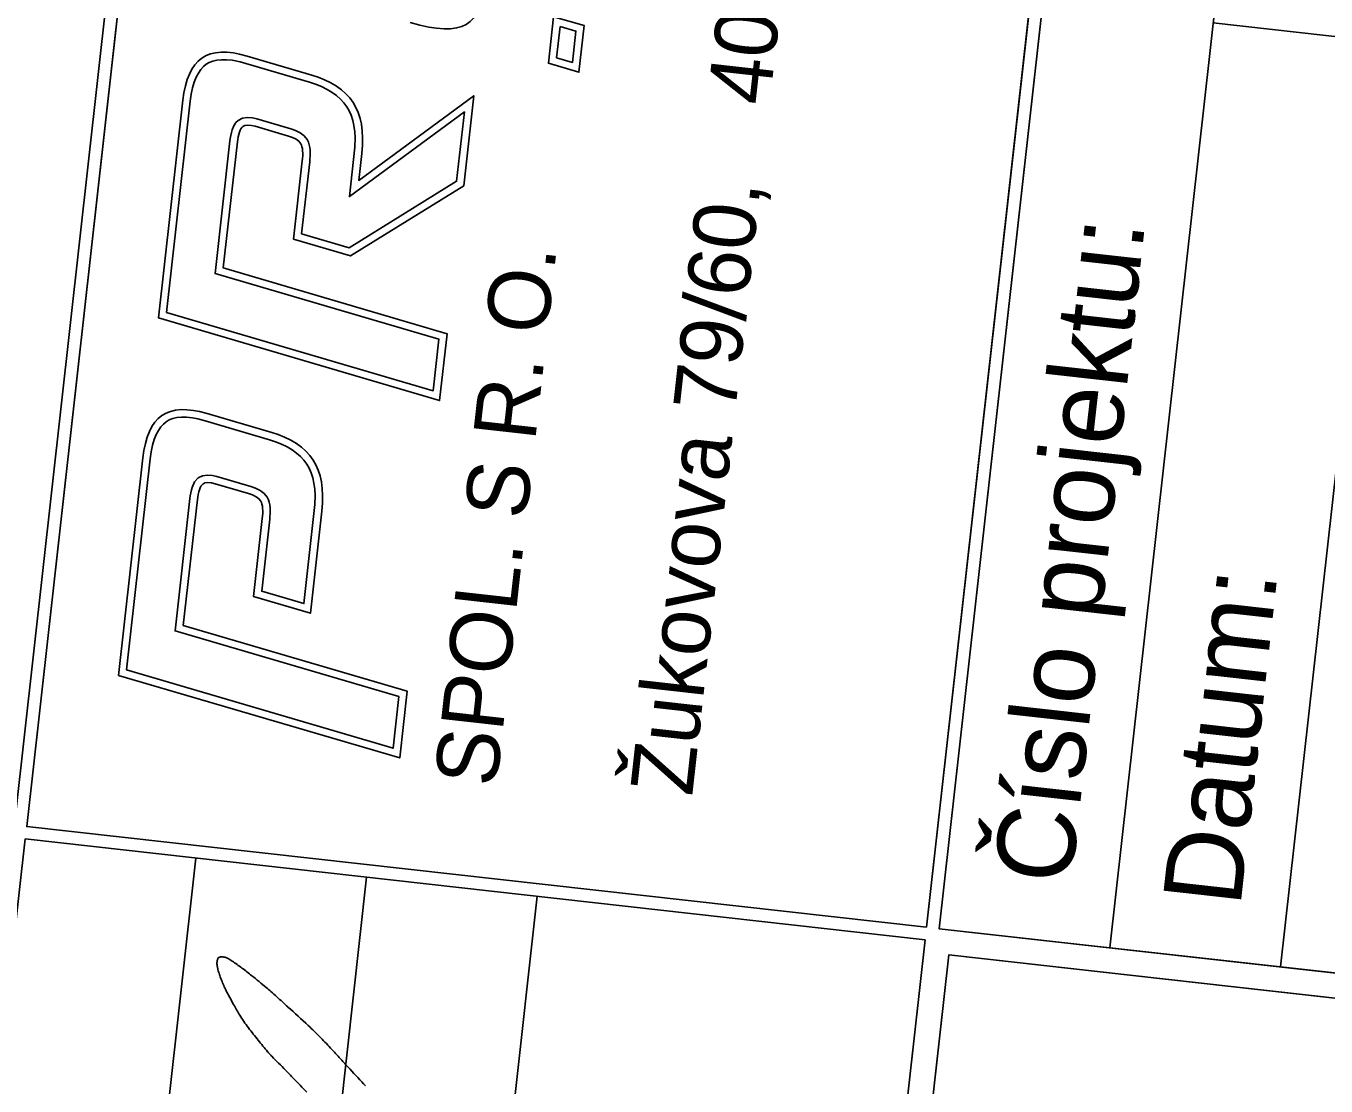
# Model space of a CAD drawing. Extents: x -734953 to -734775, y -1144697 to -1144368.
# Drawn here: x -734813.98 to -734794.21, y -1144416.34 to -1144400.21 of the extents above; entities that cross this region are included whole.
import ezdxf

# ---------------------------------------------------------------- set-up
doc = ezdxf.new("R2010")
doc.units = 0
doc.layers.add('000_rozpiska', color=7, linetype='Continuous')

# ---------------------------------------------------------------- blocks, each defined once
blk = doc.blocks.new('A$C2B726605')
at = {"layer": '000_rozpiska'}
for p, q in [((-8.894, 71.716), (-181.794, 71.716)), ((-8.894, 71.716), (-181.794, 71.716)), ((-63.424, 43.784), (-63.424, 71.336)), ((-8.894, 71.336), (-63.044, 71.336)), ((-63.044, 43.784), (-63.044, 71.336)), ((-59.709, 60.291), (-58.162, 69.071)), ((-58.164, 69.072), (-51.5, 69.072)), ((-48.767, 60.291), (-47.22, 69.071)), ((-47.222, 69.072), (-40.558, 69.072)), ((-56.434, 67.282), (-57.665, 60.291)), ((-56.434, 67.282), (-52.576, 67.282)), ((-49.947, 67.282), (-50.304, 65.256)), ((-45.492, 67.282), (-46.723, 60.291)), ((-45.492, 67.282), (-41.634, 67.282)), ((-39.005, 67.282), (-39.362, 65.256)), ((-52.042, 66.796), (-52.226, 65.755)), ((-41.1, 66.796), (-41.284, 65.755)), ((-63.424, 66.111), (-184.264, 66.111)), ((-55.325, 65.256), (-55.638, 63.481)), ((-55.325, 65.256), (-52.933, 65.256)), ((-44.383, 65.256), (-44.696, 63.481)), ((-44.383, 65.256), (-41.991, 65.256)), ((-55.638, 63.481), (-52.508, 63.481)), ((-42.191, 60.291), (-44.696, 63.481)), ((-42.389, 63.481), (-41.567, 63.481)), ((-39.439, 60.291), (-42.389, 63.481)), ((-63.424, 60.886), (-184.264, 60.886)), ((-57.665, 60.291), (-59.709, 60.291)), ((-46.723, 60.291), (-48.767, 60.291)), ((-39.439, 60.291), (-42.191, 60.291)), ((-38.371, 57.193), (-38.204, 58.143)), ((-36.779, 58.143), (-38.204, 58.143)), ((-38.099, 57.421), (-38.012, 57.915)), ((-37.05, 57.915), (-38.012, 57.915)), ((-37.137, 57.421), (-37.05, 57.915)), ((-37.137, 57.421), (-38.099, 57.421)), ((-36.946, 57.193), (-38.371, 57.193)), ((-63.424, 55.661), (-184.264, 55.661)), ((-63.424, 43.784), (-184.264, 43.784)), ((-184.264, 43.784), (-63.424, 43.784)), ((-6.424, 43.784), (-63.044, 43.784)), ((-63.044, 43.404), (-63.044, 22.504)), ((-6.424, 43.404), (-63.044, 43.404)), ((-183.884, 43.024), (-63.804, 43.024)), ((-63.804, 43.024), (-63.804, 6.804)), ((-6.424, 38.179), (-63.044, 38.179)), ((-34.734, 32.954), (-34.734, 38.179)), ((-6.424, 32.954), (-63.044, 32.954))]:
    blk.add_line(p, q, dxfattribs=at)
for points in [[(-181.794, 71.336), (-63.424, 71.336), (-63.424, 43.784)], [(-63.044, 43.784), (-63.044, 71.336), (-8.894, 71.336)], [(-63.424, 43.784), (-184.264, 43.784), (-184.264, 68.866)], [(-6.424, 68.866), (-6.424, 43.784), (-63.044, 43.784)], [(-50.687, 68.963), (-50.864, 69.011), (-51.061, 69.045), (-51.275, 69.066), (-51.5, 69.072), (-58.162, 69.072), (-59.709, 60.291), (-57.665, 60.291), (-56.434, 67.282), (-52.576, 67.282), (-52.505, 67.28), (-52.422, 67.276), (-52.344, 67.267), (-52.276, 67.256), (-52.217, 67.241), (-52.168, 67.222), (-52.127, 67.2), (-52.095, 67.174), (-52.054, 67.111), (-52.032, 67.026), (-52.029, 66.916), (-52.042, 66.796), (-52.226, 65.755), (-52.255, 65.629), (-52.298, 65.515), (-52.35, 65.426), (-52.415, 65.36), (-52.455, 65.336), (-52.502, 65.314), (-52.56, 65.295), (-52.624, 65.281), (-52.698, 65.269), (-52.772, 65.261), (-52.862, 65.257), (-52.933, 65.256), (-55.325, 65.256), (-55.638, 63.481), (-52.508, 63.481), (-52.255, 63.488), (-52.029, 63.509), (-51.827, 63.542), (-51.622, 63.593), (-51.452, 63.651), (-51.281, 63.729), (-51.133, 63.816), (-50.997, 63.915), (-50.866, 64.032), (-50.752, 64.167), (-50.649, 64.314), (-50.556, 64.477), (-50.474, 64.657), (-50.402, 64.856), (-50.345, 65.063), (-50.304, 65.256), (-49.947, 67.282), (-49.913, 67.52), (-49.899, 67.704), (-49.903, 67.903), (-49.918, 68.079), (-49.956, 68.245), (-50.007, 68.389), (-50.075, 68.522), (-50.163, 68.638), (-50.267, 68.739), (-50.389, 68.827), (-50.531, 68.902), (-50.687, 68.963)], [(-57.971, 68.844), (-51.507, 68.844), (-51.29, 68.838), (-51.091, 68.819), (-50.914, 68.788), (-50.758, 68.746), (-50.626, 68.695), (-50.51, 68.633), (-50.414, 68.564), (-50.335, 68.487), (-50.269, 68.4), (-50.217, 68.298), (-50.175, 68.181), (-50.144, 68.044), (-50.131, 67.891), (-50.127, 67.711), (-50.14, 67.545), (-50.172, 67.318), (-50.527, 65.303), (-50.567, 65.117), (-50.62, 64.925), (-50.685, 64.743), (-50.759, 64.581), (-50.842, 64.437), (-50.933, 64.306), (-51.03, 64.192), (-51.141, 64.092), (-51.258, 64.007), (-51.386, 63.932), (-51.537, 63.863), (-51.686, 63.812), (-51.873, 63.766), (-52.059, 63.735), (-52.334, 63.709), (-55.366, 63.709), (-55.134, 65.028), (-52.929, 65.028), (-52.855, 65.029), (-52.755, 65.034), (-52.668, 65.043), (-52.581, 65.056), (-52.499, 65.075), (-52.418, 65.102), (-52.348, 65.135), (-52.272, 65.18), (-52.168, 65.287), (-52.092, 65.417), (-52.036, 65.563), (-52.002, 65.71), (-51.816, 66.77), (-51.8, 66.907), (-51.805, 67.058), (-51.843, 67.204), (-51.923, 67.328), (-52.052, 67.434), (-52.229, 67.479), (-52.312, 67.493), (-52.404, 67.503), (-52.497, 67.508), (-52.57, 67.51), (-56.625, 67.51), (-57.857, 60.519), (-59.437, 60.519), (-57.971, 68.844)], [(-50.144, 68.044), (-50.175, 68.181), (-50.217, 68.298), (-50.269, 68.4), (-50.335, 68.487), (-50.414, 68.564), (-50.51, 68.633), (-50.626, 68.695), (-50.758, 68.746), (-50.914, 68.788), (-51.091, 68.819), (-51.29, 68.838), (-51.507, 68.844), (-57.971, 68.844), (-59.437, 60.519), (-57.857, 60.519), (-56.625, 67.51), (-52.57, 67.51), (-52.497, 67.508), (-52.404, 67.503), (-52.312, 67.493), (-52.229, 67.479), (-52.052, 67.434), (-51.923, 67.328), (-51.843, 67.204), (-51.805, 67.058), (-51.8, 66.907), (-51.816, 66.77), (-52.002, 65.71), (-52.036, 65.563), (-52.092, 65.417), (-52.168, 65.287), (-52.272, 65.18), (-52.348, 65.135), (-52.418, 65.102), (-52.499, 65.075), (-52.581, 65.056), (-52.668, 65.043), (-52.755, 65.034), (-52.855, 65.029), (-52.929, 65.028), (-55.134, 65.028), (-55.366, 63.709), (-52.334, 63.709), (-52.059, 63.735), (-51.873, 63.766), (-51.686, 63.812), (-51.537, 63.863), (-51.386, 63.932), (-51.258, 64.007), (-51.141, 64.092), (-51.03, 64.192), (-50.933, 64.306), (-50.842, 64.437), (-50.759, 64.581), (-50.685, 64.743), (-50.62, 64.925), (-50.567, 65.117), (-50.527, 65.303), (-50.172, 67.318), (-50.14, 67.545), (-50.127, 67.711), (-50.131, 67.891), (-50.144, 68.044)], [(-56.625, 67.51), (-57.857, 60.519), (-59.437, 60.519), (-57.971, 68.844), (-51.507, 68.844), (-51.29, 68.838), (-51.091, 68.819), (-50.914, 68.788), (-50.758, 68.746), (-50.626, 68.695), (-50.51, 68.633), (-50.414, 68.564), (-50.335, 68.487), (-50.269, 68.4), (-50.217, 68.298), (-50.175, 68.181), (-50.144, 68.044), (-50.131, 67.891), (-50.127, 67.711), (-50.14, 67.545), (-50.172, 67.318), (-50.527, 65.303), (-50.567, 65.117), (-50.62, 64.925), (-50.685, 64.743), (-50.759, 64.581), (-50.842, 64.437), (-50.933, 64.306), (-51.03, 64.192), (-51.141, 64.092), (-51.258, 64.007), (-51.386, 63.932), (-51.537, 63.863), (-51.686, 63.812), (-51.873, 63.766), (-52.059, 63.735), (-52.334, 63.709), (-55.366, 63.709), (-55.134, 65.028), (-52.929, 65.028), (-52.855, 65.029), (-52.755, 65.034), (-52.668, 65.043), (-52.581, 65.056), (-52.499, 65.075), (-52.418, 65.102), (-52.348, 65.135), (-52.272, 65.18), (-52.168, 65.287), (-52.092, 65.417), (-52.036, 65.563), (-52.002, 65.71), (-51.816, 66.77), (-51.8, 66.907), (-51.805, 67.058), (-51.843, 67.204), (-51.923, 67.328), (-52.052, 67.434), (-52.229, 67.479), (-52.312, 67.493), (-52.404, 67.503), (-52.497, 67.508), (-52.57, 67.51), (-56.625, 67.51)], [(-51.5, 69.072), (-51.275, 69.066), (-51.061, 69.045), (-50.864, 69.011), (-50.687, 68.963), (-50.531, 68.902), (-50.389, 68.827), (-50.267, 68.739), (-50.163, 68.638), (-50.075, 68.522), (-50.007, 68.389), (-49.956, 68.245), (-49.918, 68.079), (-49.903, 67.903), (-49.899, 67.704), (-49.913, 67.52), (-49.947, 67.282)], [(-38.971, 67.52), (-38.957, 67.704), (-38.961, 67.903), (-38.976, 68.079), (-39.014, 68.245), (-39.065, 68.389), (-39.133, 68.522), (-39.221, 68.638), (-39.325, 68.739), (-39.447, 68.827), (-39.589, 68.902), (-39.745, 68.963), (-39.922, 69.011), (-40.119, 69.045), (-40.333, 69.066), (-40.558, 69.072), (-47.22, 69.072), (-48.767, 60.291), (-46.723, 60.291), (-45.492, 67.282), (-41.634, 67.282), (-41.563, 67.28), (-41.48, 67.276), (-41.402, 67.267), (-41.334, 67.256), (-41.275, 67.241), (-41.226, 67.222), (-41.185, 67.2), (-41.153, 67.174), (-41.112, 67.111), (-41.09, 67.026), (-41.087, 66.916), (-41.1, 66.796), (-41.284, 65.755), (-41.313, 65.629), (-41.356, 65.515), (-41.408, 65.426), (-41.473, 65.36), (-41.513, 65.336), (-41.56, 65.314), (-41.618, 65.295), (-41.682, 65.281), (-41.756, 65.269), (-41.83, 65.261), (-41.92, 65.257), (-41.991, 65.256), (-44.383, 65.256), (-44.696, 63.481), (-42.191, 60.291), (-39.439, 60.291), (-42.389, 63.481), (-41.567, 63.481), (-41.313, 63.488), (-41.087, 63.509), (-40.885, 63.542), (-40.68, 63.593), (-40.51, 63.651), (-40.339, 63.729), (-40.191, 63.816), (-40.055, 63.915), (-39.924, 64.032), (-39.81, 64.167), (-39.707, 64.314), (-39.614, 64.477), (-39.532, 64.657), (-39.46, 64.856), (-39.403, 65.063), (-39.362, 65.256), (-39.005, 67.282), (-38.971, 67.52)], [(-45.683, 67.51), (-46.915, 60.519), (-48.495, 60.519), (-47.029, 68.844), (-40.565, 68.844), (-40.348, 68.838), (-40.149, 68.819), (-39.972, 68.788), (-39.817, 68.746), (-39.684, 68.695), (-39.568, 68.633), (-39.472, 68.564), (-39.393, 68.487), (-39.327, 68.4), (-39.275, 68.298), (-39.233, 68.181), (-39.202, 68.044), (-39.189, 67.891), (-39.185, 67.711), (-39.203, 67.472), (-39.585, 65.303), (-39.625, 65.117), (-39.678, 64.925), (-39.743, 64.743), (-39.817, 64.581), (-39.9, 64.437), (-39.991, 64.306), (-40.088, 64.192), (-40.199, 64.092), (-40.316, 64.007), (-40.444, 63.932), (-40.595, 63.863), (-40.744, 63.812), (-40.931, 63.766), (-41.117, 63.735), (-41.392, 63.709), (-42.91, 63.709), (-39.96, 60.519), (-42.08, 60.519), (-44.454, 63.542), (-44.192, 65.028), (-41.987, 65.028), (-41.913, 65.029), (-41.813, 65.034), (-41.726, 65.043), (-41.639, 65.056), (-41.557, 65.075), (-41.476, 65.102), (-41.406, 65.135), (-41.33, 65.18), (-41.226, 65.287), (-41.15, 65.417), (-41.094, 65.563), (-41.06, 65.71), (-40.874, 66.77), (-40.858, 66.907), (-40.863, 67.058), (-40.901, 67.204), (-40.981, 67.328), (-41.057, 67.39), (-41.162, 67.447), (-41.287, 67.479), (-41.37, 67.493), (-41.462, 67.503), (-41.555, 67.508), (-41.628, 67.51), (-45.683, 67.51)], [(-39.275, 68.298), (-39.327, 68.4), (-39.393, 68.487), (-39.472, 68.564), (-39.568, 68.633), (-39.684, 68.695), (-39.817, 68.746), (-39.972, 68.788), (-40.149, 68.819), (-40.348, 68.838), (-40.565, 68.844), (-47.029, 68.844), (-48.495, 60.519), (-46.915, 60.519), (-45.683, 67.51), (-41.628, 67.51), (-41.555, 67.508), (-41.462, 67.503), (-41.37, 67.493), (-41.287, 67.479), (-41.162, 67.447), (-41.057, 67.39), (-40.981, 67.328), (-40.901, 67.204), (-40.863, 67.058), (-40.858, 66.907), (-40.874, 66.77), (-41.06, 65.71), (-41.094, 65.563), (-41.15, 65.417), (-41.226, 65.287), (-41.33, 65.18), (-41.406, 65.135), (-41.476, 65.102), (-41.557, 65.075), (-41.639, 65.056), (-41.726, 65.043), (-41.813, 65.034), (-41.913, 65.029), (-41.987, 65.028), (-44.192, 65.028), (-44.454, 63.542), (-42.08, 60.519), (-39.96, 60.519), (-42.91, 63.709), (-41.392, 63.709), (-41.117, 63.735), (-40.931, 63.766), (-40.744, 63.812), (-40.595, 63.863), (-40.444, 63.932), (-40.316, 64.007), (-40.199, 64.092), (-40.088, 64.192), (-39.991, 64.306), (-39.9, 64.437), (-39.817, 64.581), (-39.743, 64.743), (-39.678, 64.925), (-39.625, 65.117), (-39.585, 65.303), (-39.203, 67.472), (-39.185, 67.711), (-39.189, 67.891), (-39.202, 68.044), (-39.233, 68.181), (-39.275, 68.298)], [(-45.683, 67.51), (-46.915, 60.519), (-48.495, 60.519), (-47.029, 68.844), (-40.565, 68.844), (-40.348, 68.838), (-40.149, 68.819), (-39.972, 68.788), (-39.817, 68.746), (-39.684, 68.695), (-39.568, 68.633), (-39.472, 68.564), (-39.393, 68.487), (-39.327, 68.4), (-39.275, 68.298), (-39.233, 68.181), (-39.202, 68.044), (-39.189, 67.891), (-39.185, 67.711), (-39.203, 67.472), (-39.585, 65.303), (-39.625, 65.117), (-39.678, 64.925), (-39.743, 64.743), (-39.817, 64.581), (-39.9, 64.437), (-39.991, 64.306), (-40.088, 64.192), (-40.199, 64.092), (-40.316, 64.007), (-40.444, 63.932), (-40.595, 63.863), (-40.744, 63.812), (-40.931, 63.766), (-41.117, 63.735), (-41.392, 63.709), (-42.91, 63.709), (-39.96, 60.519), (-42.08, 60.519), (-44.454, 63.542), (-44.192, 65.028), (-41.987, 65.028), (-41.913, 65.029), (-41.813, 65.034), (-41.726, 65.043), (-41.639, 65.056), (-41.557, 65.075), (-41.476, 65.102), (-41.406, 65.135), (-41.33, 65.18), (-41.226, 65.287), (-41.15, 65.417), (-41.094, 65.563), (-41.06, 65.71), (-40.874, 66.77), (-40.858, 66.907), (-40.863, 67.058), (-40.901, 67.204), (-40.981, 67.328), (-41.057, 67.39), (-41.162, 67.447), (-41.287, 67.479), (-41.37, 67.493), (-41.462, 67.503), (-41.555, 67.508), (-41.628, 67.51), (-45.683, 67.51)], [(-40.558, 69.072), (-40.333, 69.066), (-40.119, 69.045), (-39.922, 69.011), (-39.745, 68.963), (-39.589, 68.902), (-39.447, 68.827), (-39.325, 68.739), (-39.221, 68.638), (-39.133, 68.522), (-39.065, 68.389), (-39.014, 68.245), (-38.976, 68.079), (-38.961, 67.903), (-38.957, 67.704), (-38.971, 67.52), (-39.005, 67.282)], [(-37.489, 62.162), (-37.516, 61.886), (-37.526, 61.641), (-37.518, 61.417), (-37.493, 61.216), (-37.449, 61.041), (-37.388, 60.887), (-37.309, 60.758)], [(-52.217, 67.241), (-52.276, 67.256), (-52.344, 67.267), (-52.422, 67.276), (-52.505, 67.28), (-52.576, 67.282)], [(-52.042, 66.796), (-52.029, 66.916), (-52.032, 67.026), (-52.054, 67.111), (-52.095, 67.174), (-52.127, 67.2), (-52.168, 67.222), (-52.217, 67.241)], [(-41.275, 67.241), (-41.334, 67.256), (-41.402, 67.267), (-41.48, 67.276), (-41.563, 67.28), (-41.634, 67.282)], [(-41.1, 66.796), (-41.087, 66.916), (-41.09, 67.026), (-41.112, 67.111), (-41.153, 67.174), (-41.185, 67.2), (-41.226, 67.222), (-41.275, 67.241)], [(-52.226, 65.755), (-52.255, 65.629), (-52.298, 65.515), (-52.35, 65.426), (-52.415, 65.36), (-52.455, 65.336), (-52.502, 65.314), (-52.56, 65.295), (-52.624, 65.281), (-52.698, 65.269), (-52.772, 65.261), (-52.862, 65.257), (-52.933, 65.256)], [(-41.284, 65.755), (-41.313, 65.629), (-41.356, 65.515), (-41.408, 65.426), (-41.473, 65.36), (-41.513, 65.336), (-41.56, 65.314), (-41.618, 65.295), (-41.682, 65.281), (-41.756, 65.269), (-41.83, 65.261), (-41.92, 65.257), (-41.991, 65.256)], [(-50.304, 65.256), (-50.345, 65.063), (-50.402, 64.856), (-50.474, 64.657), (-50.556, 64.477), (-50.649, 64.314), (-50.752, 64.167), (-50.866, 64.032), (-50.997, 63.915), (-51.133, 63.816), (-51.281, 63.729), (-51.452, 63.651), (-51.622, 63.593), (-51.827, 63.542), (-52.029, 63.509), (-52.255, 63.488), (-52.508, 63.481)], [(-39.362, 65.256), (-39.403, 65.063), (-39.46, 64.856), (-39.532, 64.657), (-39.614, 64.477), (-39.707, 64.314), (-39.81, 64.167), (-39.924, 64.032), (-40.055, 63.915), (-40.191, 63.816), (-40.339, 63.729), (-40.51, 63.651), (-40.68, 63.593), (-40.885, 63.542), (-41.087, 63.509), (-41.313, 63.488), (-41.567, 63.481)], [(-35.752, 60.291), (-36.071, 60.299), (-36.323, 60.321), (-36.552, 60.357), (-36.755, 60.409), (-36.933, 60.474), (-37.082, 60.554), (-37.209, 60.649), (-37.309, 60.758), (-37.388, 60.887), (-37.449, 61.041), (-37.493, 61.216), (-37.518, 61.417), (-37.526, 61.641), (-37.516, 61.886), (-37.489, 62.162), (-37.443, 62.463)], [(-36.779, 58.143), (-38.204, 58.143), (-38.371, 57.193), (-36.946, 57.193), (-36.779, 58.143)], [(-37.05, 57.915), (-37.137, 57.421), (-38.099, 57.421), (-38.012, 57.915), (-37.05, 57.915)], [(-37.05, 57.915), (-38.012, 57.915), (-38.099, 57.421), (-37.137, 57.421), (-37.05, 57.915)], [(-63.044, 22.504), (-63.044, 43.404), (-6.424, 43.404), (-6.424, 22.504), (-63.044, 22.504)], [(-183.884, 8.894), (-183.884, 43.024), (-63.804, 43.024), (-63.804, 6.804)]]:
    blk.add_lwpolyline(points, dxfattribs=at)
for s, height, p in [('SPOL. S R. O.', 1.9, (-60.29, 57.265)), ('Žukovova 79/60, ', 1.9, (-59.898, 51.316)), ('400 03 Ústí nad', 1.9, (-38.76, 51.316)), ('Číslo projektu:', 2.375, (-61.304, 39.558)), ('Datum:', 2.375, (-61.395, 34.367))]:
    blk.add_text(s, height=height, dxfattribs=at).set_placement(p)
blk = doc.blocks.new('Vodnansky')
at = {"layer": '000_rozpiska'}
for centre, radius, start, end in [((32.368, 5.451), 4.734, 118.015, 120.1722), ((31.187, 7.671), 2.219, 114.0617, 118.015), ((31.415, 7.161), 2.778, 110.5285, 114.0617), ((30.922, 8.476), 1.373, 105.9368, 110.5285), ((30.714, 9.206), 0.615, 99.071, 105.9368), ((30.663, 9.522), 0.295, 91.7892, 99.071), ((30.681, 8.967), 0.849, 87.5025, 91.7892), ((30.706, 9.54), 0.276, 75.9718, 87.5025), ((30.744, 9.693), 0.118, 58.2999, 75.9718), ((30.775, 9.744), 0.0579, 29.4928, 58.2999), ((30.124, 9.751), 0.746, 338.4462, 346.7254), ((30.637, 9.666), 0.217, 14.7156, 29.4928), ((30.54, 9.641), 0.317, 1.2743, 14.7156), ((30.586, 9.642), 0.271, 346.7254, 1.2743), ((38.712, -3.99), 16.109, 124.2098, 125.4138), ((33.421, 3.793), 6.698, 122.3426, 124.2098), ((32.339, 5.501), 4.676, 120.1722, 122.3426), ((23.353, 13.194), 8.345, 329.86, 332.4981), ((29.474, 10.008), 1.445, 332.4981, 338.4462), ((32.305, 4.832), 5.209, 131.1576, 133.9214), ((31.348, 5.927), 3.755, 127.5601, 131.1576), ((35.488, 0.543), 10.547, 125.4138, 127.5601), ((22.597, 13.633), 9.219, 327.3501, 329.86), ((43.563, -6.858), 21.439, 133.9214, 135.2837), ((-9.671, 34.309), 47.543, 326.6355, 327.3501), ((53.331, -16.53), 35.185, 135.2837, 136.0545), ((-8.399, 35.306), 47.058, 324.2166, 324.5251), ((25.484, 11.16), 5.451, 324.5251, 326.6355), ((-103.222, 113.841), 168.649, 320.80219, 321.01297), ((31.364, 4.906), 4.499, 139.7224, 141.013), ((29.118, 6.809), 1.555, 136.0545, 139.7224), ((-108.895, 107.742), 170.939, 324.05473, 324.21659), ((-6.744, 35.161), 44.157, 320.3195, 320.8022), ((-88.457, 92.923), 145.693, 323.70868, 324.05473), ((-63.693, 82.408), 118.153, 320.02436, 320.31946), ((18.755, 14.192), 12.678, 322.5356, 323.7087), ((10.583, 21.194), 23.435, 319.1032, 320.3663), ((22.512, 11.314), 7.945, 320.3663, 322.5356), ((-171.142, 178.591), 263.846, 319.00098, 319.10323), ((163.875, -112.624), 180.048, 139.00098, 139.12475), ((246.391, -184.04), 289.177, 139.12475, 139.26937)]:
    blk.add_arc(centre, radius, start, end, dxfattribs=at)

msp = doc.modelspace()

# ---------------------------------------------------------------- block references
at = {"layer": '000_rozpiska', "rotation": 83.61482079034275}
for name, p, xscale, yscale in [('A$C2B726605', (-734775.02, -1144385.03), 0.4999999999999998, 0.4999999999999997), ('Vodnansky', (-734808.063, -1144429.447), 0.4749999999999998, 0.47499999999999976)]:
    msp.add_blockref(name, p, dxfattribs=dict(at, xscale=xscale, yscale=yscale))

doc.saveas('drawing.dxf')
